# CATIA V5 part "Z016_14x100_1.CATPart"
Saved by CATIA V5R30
Part number: SIKMY KOLIK KUZELOVY 18° D14
Bounding box of the stored display mesh (mm): x -8 to 92, y -9 to 9, z -9 to 9
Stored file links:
  C:\Users\ondra\Desktop\PŘÍLOHA P III\CATIA\Z016_14x100_1.CATPart
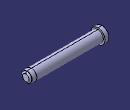
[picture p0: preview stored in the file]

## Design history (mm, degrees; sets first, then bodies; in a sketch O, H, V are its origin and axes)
Set1
  DatumSurface1 to DatumSurface14 "Z016/14x"
  Point1: type OnSurface, Support DatumSurface14, Length 0, Direction edge of DatumSurface13
  Plane1: type Tangent, Support DatumSurface14, RefPoint Point1
  Join1: Elements (DatumSurface1; DatumSurface2; DatumSurface3; DatumSurface4; DatumSurface5; DatumSurface6; DatumSurface7; DatumSurface8; DatumSurface9; DatumSurface10; DatumSurface11; DatumSurface12; DatumSurface13; DatumSurface14)
Body1 (main body)
  CloseSurface1: CloseElement Join1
